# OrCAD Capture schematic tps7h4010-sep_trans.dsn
size Custom; title: TPS7H4010-SEP Radiation Hardened 3.5-V to 32-V, 6-A; rev: A; note: Datasheet: SNVSBL0A    EVM: SNVU744; note: Synchronous Step-Down Converter in Space Enhanced Plastic
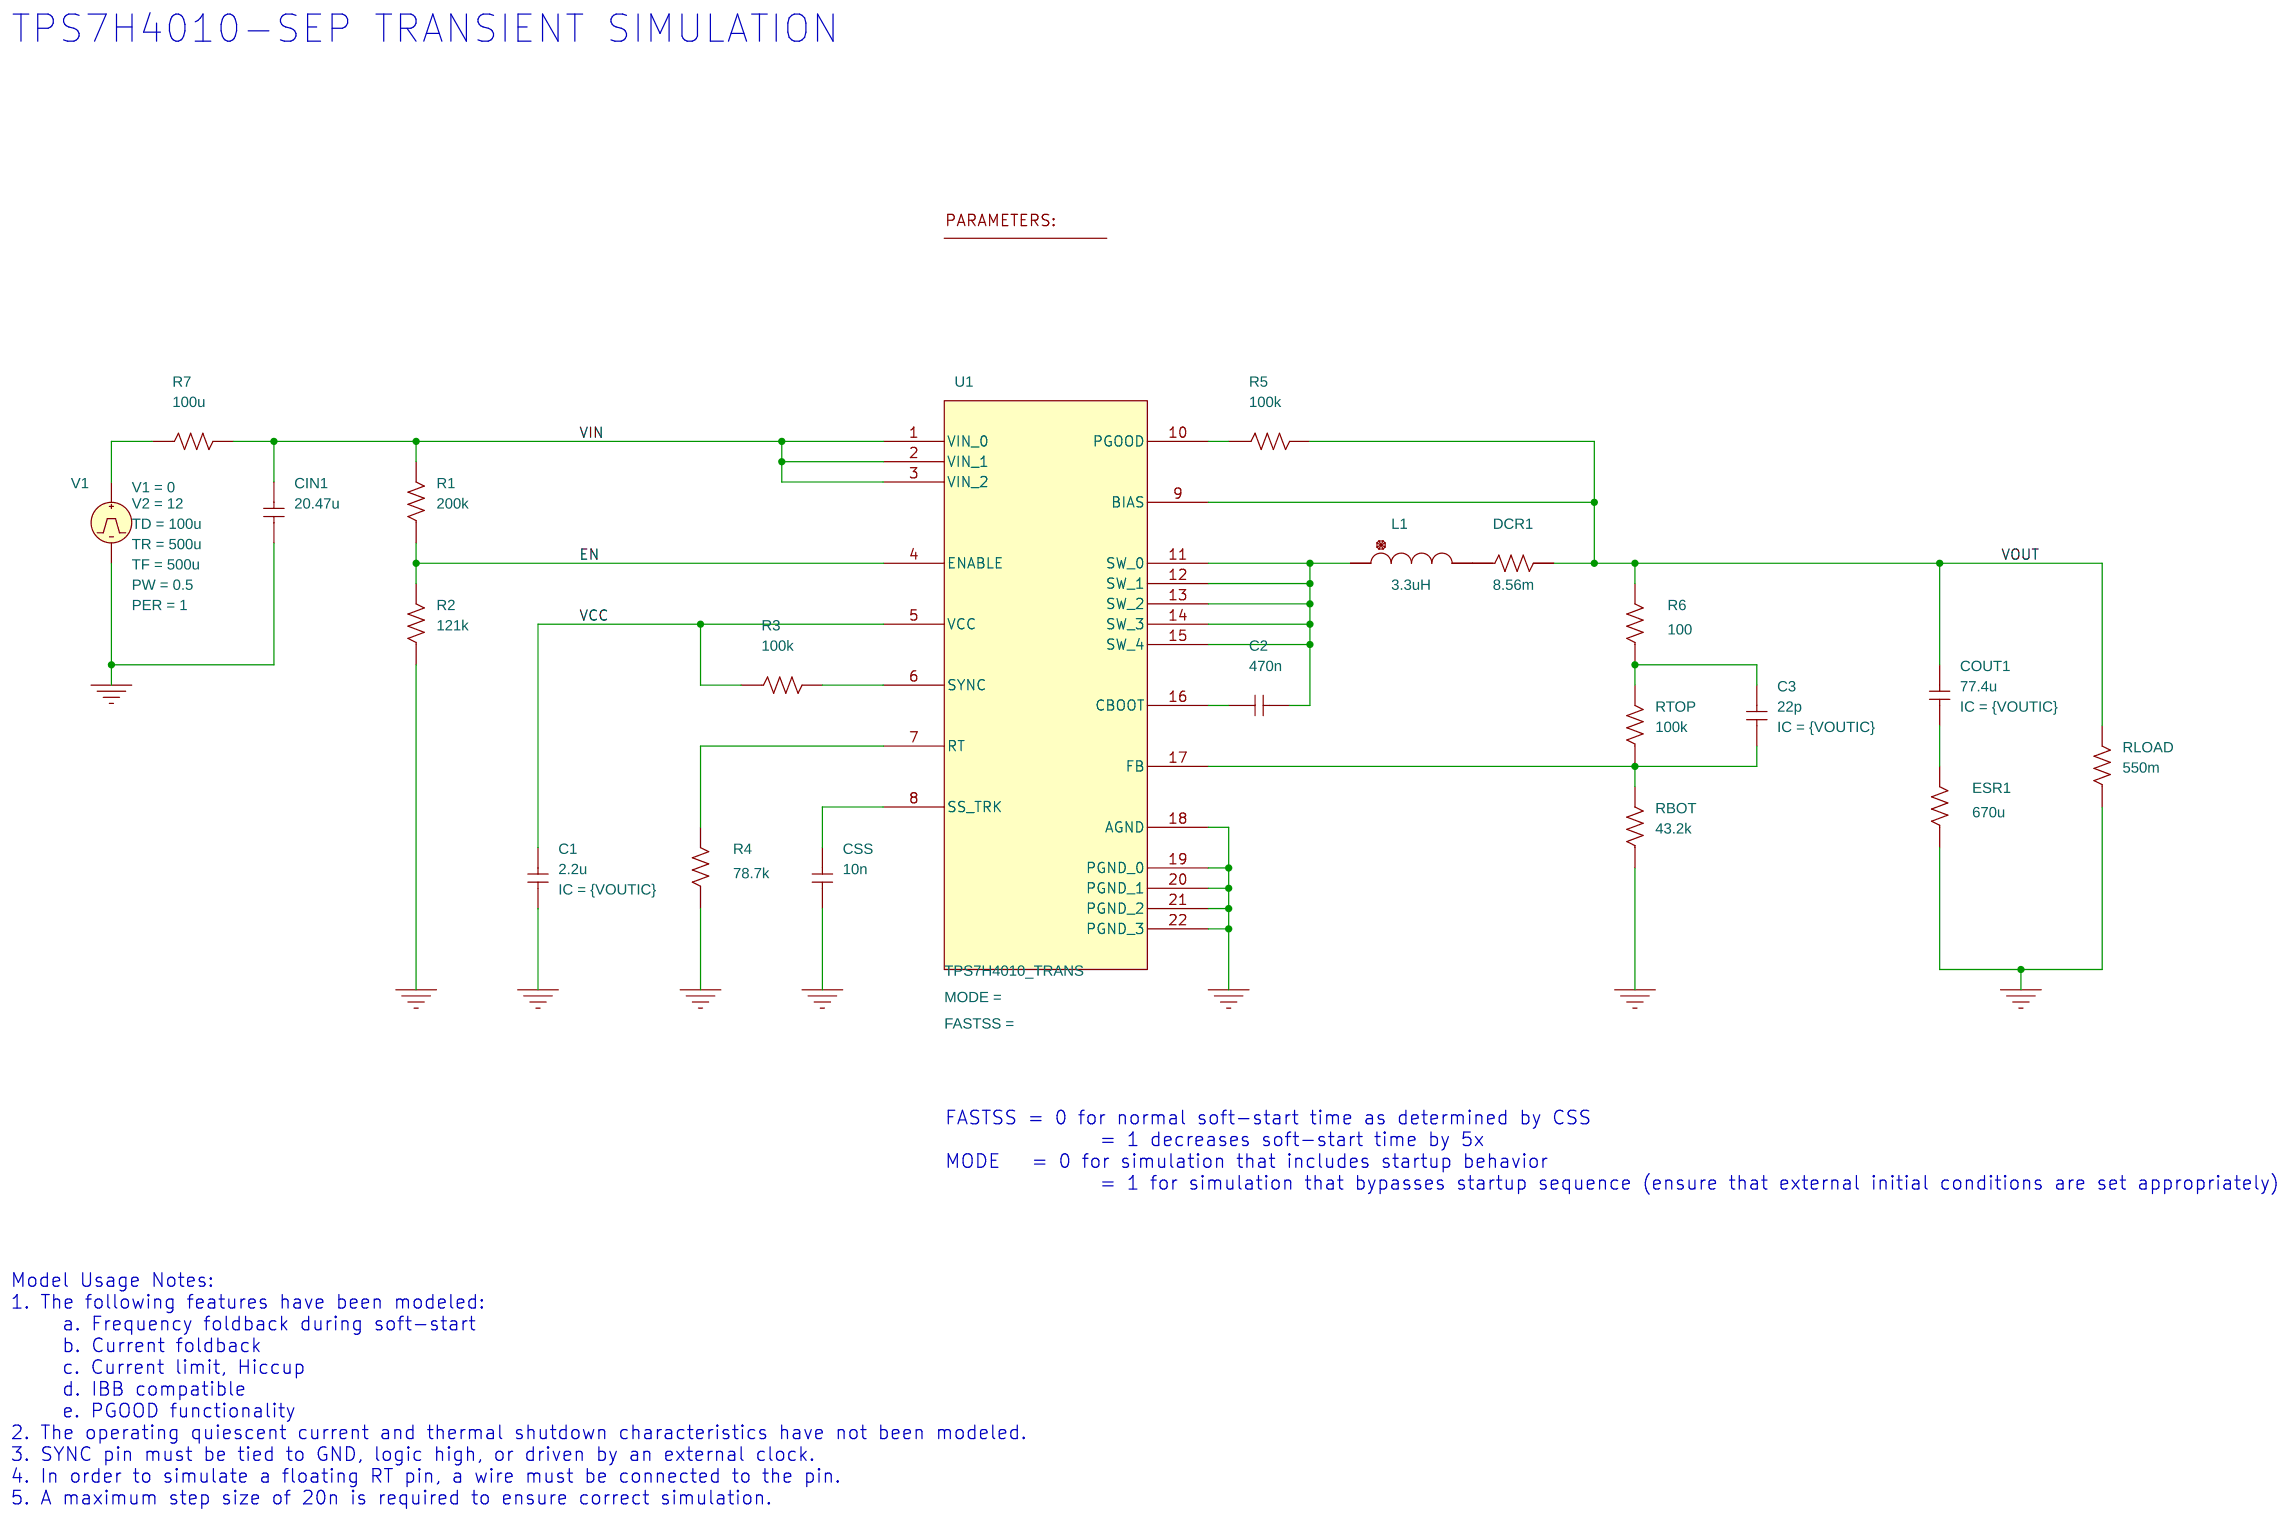
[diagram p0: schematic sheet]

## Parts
1  PARAM
C1  2.2u  [cap196]
C2  470n  [cap196]
C3  22p  [cap196]
CIN1  20.47u  [cap196]
COUT1  77.4u  [cap196]
CSS  10n  [cap196]
DCR1  8.56m  [AXRC05]
ESR1  670u  [AXRC05]
L1  3.3uH  [DISC350x175LS200x100034]
R1  200k  [AXRC05]
R2  121k  [AXRC05]
R3  100k  [AXRC05]
R4  78.7k  [AXRC05]
R5  100k  [AXRC05]
R6  100  [AXRC05]
R7  100u  [AXRC05]
RBOT  43.2k  [AXRC05]
RLOAD  550m  [AXRC05]
RTOP  100k  [AXRC05]
U1  TPS7H4010_TRANS
V1  VPULSE

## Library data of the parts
1 = PARAM: VOUTIC: 0
C1 C3 COUT1 = C: IC: {VOUTIC}
C2 CIN1 CSS = C
DCR1 ESR1 R1-R7 RBOT RLOAD RTOP = R
L1 = L
U1 = TPS7H4010_TRANS_4: PSpiceTemplate: X^@REFDES  %VIN_0 %VIN_1 %VIN_2 %ENABLE %VCC %SYNC %RT %SS_TRK %BIAS %PGOOD %SW_0 %SW_1 %SW_2 %SW_3 %SW_4 %CBOOT %FB %AGND %PGND_0 %PGND_1 %PGND_2 %PGND_3 @MODEL PARAMS: ?FASTSS|FASTSS=@FASTSS||FASTSS=1| ?MODE|MODE=@MODE||MODE=0|
V1 = VPULSE: PER: 1; PW: 0.5; TD: 100u; TF: 500u; TR: 500u; V1: 0; V2: 12

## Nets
VCC: C1.2 R3.1 U1.5(VCC)
VIN: CIN1.2 R1.2 R7.2 U1.1(VIN_0) U1.2(VIN_1) U1.3(VIN_2)
0: C1.1 CIN1.1 CSS.1 ESR1.1 R2.1 R4.1 RBOT.1 RLOAD.1 U1.18(AGND) U1.19(PGND_0) U1.20(PGND_1) U1.21(PGND_2) U1.22(PGND_3) V1.2(-)
EN: R1.1 R2.2 U1.4(ENABLE)
VOUT: COUT1.2 DCR1.2 R5.2 R6.2 RLOAD.2 U1.9(BIAS)
N00979: COUT1.1 ESR1.2
N01326: C3.1 RBOT.2 RTOP.1 U1.17(FB)
N03316: R4.2 U1.7(RT)
N03933: R3.2 U1.6(SYNC)
N16770630: CSS.2 U1.8(SS_TRK)
N16780836: R7.1 V1.1(+)
N16783333: C3.2 R6.1 RTOP.2
N16783522: C2.2 L1.1 U1.11(SW_0) U1.12(SW_1) U1.13(SW_2) U1.14(SW_3) U1.15(SW_4)
N16783636: C2.1 U1.16(CBOOT)
N16784094: R5.1 U1.10(PGOOD)
N16786349: DCR1.1 L1.2

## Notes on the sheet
- TPS7H4010-SEP TRANSIENT SIMULATION
- FASTSS = 0 for normal soft-start time as determined by CSS
                 = 1 decreases soft-start time by 5x
  MODE   = 0 for simulation that includes startup behavior
                 = 1 for simulation that bypasses startup sequence (ensure that external initial conditions are set appropriately)
- Model Usage Notes:
  1. The following features have been modeled:
       a. Frequency foldback during soft-start
       b. Current foldback
       c. Current limit, Hiccup
       d. IBB compatible
       e. PGOOD functionality
  2. The operating quiescent current and thermal shutdown characteristics have not been modeled.
  3. SYNC pin must be tied to GND, logic high, or driven by an external clock.
  4. In order to simulate a floating RT pin, a wire must be connected to the pin.
  5. A maximum step size of 20n is required to ensure correct simulation.
